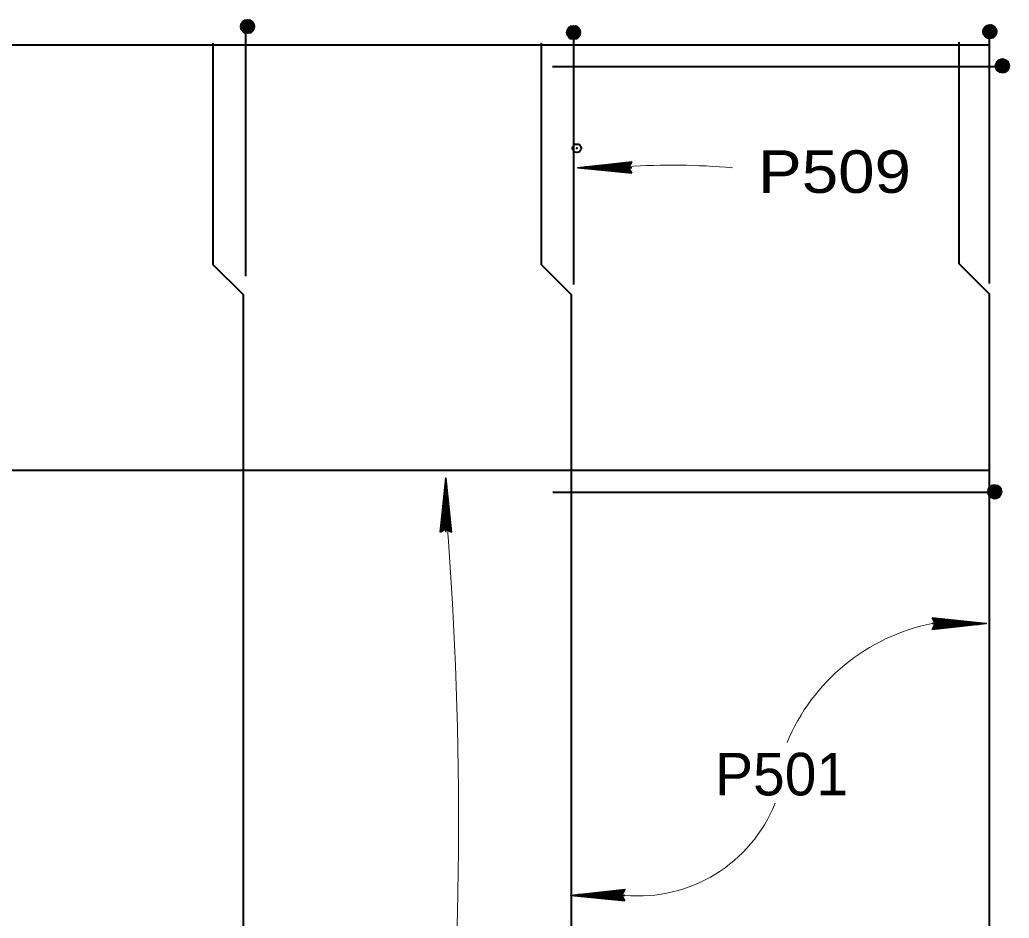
# Model space of a CAD drawing. Extents: x 6.34 to 9.53, y -1.46 to 0.53.
# Drawn here: x 7.1006 to 7.2943, y -0.5784 to -0.4024 of the extents above; entities that cross this region are included whole.
import ezdxf

# ---------------------------------------------------------------- set-up
doc = ezdxf.new("R2010")
doc.units = 0
doc.header["$LTSCALE"] = 0.0033
doc.header["$PDMODE"] = 32
doc.header["$PDSIZE"] = 0.00165
doc.layers.add('1', color=7, linetype='Continuous', lineweight=40)

msp = doc.modelspace()

# ---------------------------------------------------------------- linework, layer by layer
at = {"layer": '1'}
for p, q in [((7.14425, -0.404583), (7.144583, -0.402667)), ((7.144417, -0.404667), (7.14475, -0.402667)), ((7.1445, -0.402583), (7.146, -0.402667)), ((7.1445, -0.404667), (7.144833, -0.402667)), ((7.1445, -0.40275), (7.146, -0.402833)), ((7.1445, -0.402833), (7.146, -0.402917)), ((7.1445, -0.402917), (7.146, -0.403)), ((7.144583, -0.404667), (7.145, -0.402667)), ((7.144667, -0.404667), (7.145083, -0.402667)), ((7.144833, -0.404667), (7.145167, -0.40275)), ((7.144917, -0.40475), (7.14525, -0.40275)), ((7.145, -0.40475), (7.145417, -0.40275)), ((7.145083, -0.40475), (7.1455, -0.402833)), ((7.145167, -0.40475), (7.145583, -0.402833)), ((7.145333, -0.404833), (7.14575, -0.402833)), ((7.145583, -0.404833), (7.145917, -0.402833)), ((7.145667, -0.404833), (7.146, -0.402917)), ((7.14575, -0.404833), (7.146083, -0.402917)), ((7.145833, -0.404917), (7.146167, -0.402917)), ((7.144417, -0.403667), (7.145917, -0.40375)), ((7.144417, -0.40375), (7.145917, -0.403833)), ((7.144417, -0.403833), (7.145917, -0.403917)), ((7.144417, -0.403917), (7.145917, -0.404)), ((7.144417, -0.404), (7.145917, -0.404083)), ((7.144417, -0.404083), (7.145917, -0.404167)), ((7.144417, -0.404167), (7.145917, -0.40425)), ((7.144417, -0.404333), (7.145917, -0.404417)), ((7.144417, -0.404417), (7.145917, -0.4045)), ((7.144417, -0.4045), (7.145917, -0.404583)), ((7.144417, -0.404583), (7.145917, -0.404667)), ((7.144417, -0.404667), (7.145917, -0.40475)), ((7.1445, -0.403), (7.146, -0.403083)), ((7.1445, -0.403083), (7.146, -0.403167)), ((7.1445, -0.403167), (7.146, -0.40325)), ((7.1445, -0.40325), (7.146, -0.403333)), ((7.1445, -0.40325), (7.146, -0.403333)), ((7.1445, -0.403333), (7.146, -0.4035)), ((7.1445, -0.4035), (7.146, -0.403667)), ((7.144833, -0.403333), (7.144833, -0.452667)), ((7.208083, -0.40575), (7.208417, -0.403833)), ((7.20825, -0.405833), (7.208583, -0.403833)), ((7.20825, -0.404833), (7.20975, -0.404917)), ((7.208333, -0.40375), (7.209833, -0.403833)), ((7.208333, -0.405833), (7.208667, -0.403833)), ((7.208333, -0.403917), (7.209833, -0.404)), ((7.208333, -0.404), (7.209833, -0.404083)), ((7.208333, -0.404083), (7.209833, -0.404167)), ((7.208333, -0.404167), (7.209833, -0.40425)), ((7.208333, -0.40425), (7.209833, -0.404333)), ((7.208333, -0.404333), (7.209833, -0.404417)), ((7.208333, -0.404417), (7.209833, -0.4045)), ((7.208333, -0.404417), (7.209833, -0.4045)), ((7.208333, -0.4045), (7.209833, -0.404667)), ((7.208333, -0.404667), (7.209833, -0.404833)), ((7.208417, -0.405833), (7.208833, -0.403833)), ((7.2085, -0.405833), (7.208917, -0.403833)), ((7.208667, -0.405833), (7.209, -0.403917)), ((7.20875, -0.405917), (7.209083, -0.403917)), ((7.208833, -0.405917), (7.20925, -0.403917)), ((7.208917, -0.405917), (7.209333, -0.404)), ((7.209, -0.405917), (7.209417, -0.404)), ((7.209167, -0.406), (7.209583, -0.404)), ((7.209417, -0.406), (7.20975, -0.404)), ((7.2095, -0.406), (7.209833, -0.404083)), ((7.209583, -0.406), (7.209917, -0.404083)), ((7.209667, -0.406083), (7.21, -0.404083)), ((7.289583, -0.405583), (7.289917, -0.403667)), ((7.28975, -0.405667), (7.290083, -0.403667)), ((7.28975, -0.404667), (7.29125, -0.40475)), ((7.28975, -0.40475), (7.29125, -0.404833)), ((7.28975, -0.404833), (7.29125, -0.404917)), ((7.289833, -0.403583), (7.291333, -0.403667)), ((7.289833, -0.405667), (7.290167, -0.403667)), ((7.289833, -0.40375), (7.291333, -0.403833)), ((7.289833, -0.403833), (7.291333, -0.403917)), ((7.289833, -0.403917), (7.291333, -0.404)), ((7.289833, -0.404), (7.291333, -0.404083)), ((7.289833, -0.404083), (7.291333, -0.404167)), ((7.289833, -0.404167), (7.291333, -0.40425)), ((7.289833, -0.40425), (7.291333, -0.404333)), ((7.289833, -0.40425), (7.291333, -0.404333)), ((7.289833, -0.404333), (7.291333, -0.4045)), ((7.289833, -0.4045), (7.291333, -0.404667)), ((7.289917, -0.405667), (7.290333, -0.403667)), ((7.29, -0.405667), (7.290417, -0.403667)), ((7.290167, -0.405667), (7.2905, -0.40375)), ((7.29025, -0.40575), (7.290583, -0.40375)), ((7.290333, -0.40575), (7.29075, -0.40375)), ((7.290417, -0.40575), (7.290833, -0.403833)), ((7.290417, -0.40475), (7.290417, -0.454083)), ((7.2905, -0.40575), (7.290917, -0.403833)), ((7.290667, -0.405833), (7.291083, -0.403833)), ((7.290917, -0.405833), (7.29125, -0.403833)), ((7.291, -0.405833), (7.291333, -0.403917)), ((7.291083, -0.405833), (7.291417, -0.403917)), ((7.291167, -0.405917), (7.2915, -0.403917)), ((7.20825, -0.404917), (7.20975, -0.405)), ((7.20825, -0.405), (7.20975, -0.405083)), ((7.20825, -0.405083), (7.20975, -0.405167)), ((7.20825, -0.405167), (7.20975, -0.40525)), ((7.20825, -0.40525), (7.20975, -0.405333)), ((7.20825, -0.405333), (7.20975, -0.405417)), ((7.20825, -0.4055), (7.20975, -0.405583)), ((7.20825, -0.405583), (7.20975, -0.405667)), ((7.20825, -0.405667), (7.20975, -0.40575)), ((7.20825, -0.40575), (7.20975, -0.405833)), ((7.20825, -0.405833), (7.20975, -0.405917)), ((7.209, -0.404917), (7.209, -0.45425)), ((7.28975, -0.404917), (7.29125, -0.405)), ((7.28975, -0.405), (7.29125, -0.405083)), ((7.28975, -0.405083), (7.29125, -0.405167)), ((7.28975, -0.405167), (7.29125, -0.40525)), ((7.28975, -0.405333), (7.29125, -0.405417)), ((7.28975, -0.405417), (7.29125, -0.4055)), ((7.28975, -0.4055), (7.29125, -0.405583)), ((7.28975, -0.405583), (7.29125, -0.405667)), ((7.28975, -0.405667), (7.29125, -0.40575)), ((7.291833, -0.412167), (7.291917, -0.410667)), ((7.292, -0.412167), (7.292083, -0.410667)), ((7.292083, -0.412167), (7.292167, -0.410667)), ((7.294167, -0.410833), (7.292167, -0.4105)), ((7.294083, -0.410917), (7.292167, -0.410583)), ((7.292167, -0.412167), (7.29225, -0.410667)), ((7.294083, -0.411), (7.292167, -0.410667)), ((7.29225, -0.412167), (7.292333, -0.410667)), ((7.292333, -0.412167), (7.292417, -0.410667)), ((7.292417, -0.412167), (7.2925, -0.410667)), ((7.2925, -0.412167), (7.292583, -0.410667)), ((7.2925, -0.412167), (7.292583, -0.410667)), ((7.292583, -0.412167), (7.29275, -0.410667)), ((7.29275, -0.412167), (7.292917, -0.410667)), ((7.204917, -0.411583), (7.293, -0.411583)), ((7.207333, -0.411583), (7.293, -0.411583)), ((7.293917, -0.412), (7.291917, -0.411583)), ((7.293917, -0.412083), (7.291917, -0.411667)), ((7.293917, -0.412167), (7.291917, -0.411833)), ((7.293917, -0.41225), (7.291917, -0.411917)), ((7.293833, -0.412417), (7.291917, -0.412083)), ((7.294, -0.411667), (7.292, -0.41125)), ((7.294, -0.41175), (7.292, -0.411417)), ((7.293917, -0.411833), (7.292, -0.4115)), ((7.294083, -0.411083), (7.292083, -0.41075)), ((7.294083, -0.411333), (7.292083, -0.410917)), ((7.294, -0.4115), (7.292083, -0.411083)), ((7.294, -0.411583), (7.292083, -0.411167)), ((7.292917, -0.41225), (7.293, -0.41075)), ((7.293, -0.41225), (7.293083, -0.41075)), ((7.293083, -0.41225), (7.293167, -0.41075)), ((7.293167, -0.41225), (7.29325, -0.41075)), ((7.29325, -0.41225), (7.293333, -0.41075)), ((7.293333, -0.41225), (7.293417, -0.41075)), ((7.293417, -0.41225), (7.2935, -0.41075)), ((7.293583, -0.41225), (7.293667, -0.41075)), ((7.293667, -0.41225), (7.29375, -0.41075)), ((7.29375, -0.41225), (7.293833, -0.41075)), ((7.293833, -0.41225), (7.293917, -0.41075)), ((7.293917, -0.41225), (7.294, -0.41075)), ((6.962, -0.490667), (7.29025, -0.490667)), ((7.290667, -0.493917), (7.292583, -0.49425)), ((7.205, -0.494917), (7.290083, -0.494917)), ((7.290333, -0.4955), (7.292333, -0.495833)), ((7.290417, -0.495), (7.292417, -0.495417)), ((7.290417, -0.49525), (7.292417, -0.495583)), ((7.290417, -0.495333), (7.292333, -0.495667)), ((7.290417, -0.495417), (7.292333, -0.49575)), ((7.290583, -0.494083), (7.2905, -0.495583)), ((7.2905, -0.494583), (7.2925, -0.494917)), ((7.2905, -0.494667), (7.2925, -0.495083)), ((7.2905, -0.49475), (7.292417, -0.495167)), ((7.2905, -0.494833), (7.292417, -0.49525)), ((7.290667, -0.494083), (7.290583, -0.495583)), ((7.290583, -0.494083), (7.292583, -0.494417)), ((7.290583, -0.494167), (7.292583, -0.4945)), ((7.290583, -0.49425), (7.292583, -0.494667)), ((7.290583, -0.494333), (7.292583, -0.49475)), ((7.290583, -0.4945), (7.2925, -0.494833)), ((7.29075, -0.494083), (7.290667, -0.495583)), ((7.290833, -0.494083), (7.29075, -0.495583)), ((7.290917, -0.494083), (7.290833, -0.495583)), ((7.291083, -0.494083), (7.291, -0.495583)), ((7.291167, -0.494083), (7.291083, -0.495583)), ((7.29125, -0.494083), (7.291167, -0.495583)), ((7.291333, -0.494083), (7.29125, -0.495583)), ((7.291417, -0.494083), (7.291333, -0.495583)), ((7.2915, -0.494083), (7.291417, -0.495583)), ((7.291583, -0.494083), (7.2915, -0.495583)), ((7.29175, -0.494167), (7.291583, -0.495667)), ((7.291917, -0.494167), (7.29175, -0.495667)), ((7.292, -0.494167), (7.291917, -0.495667)), ((7.292, -0.494167), (7.291917, -0.495667)), ((7.292083, -0.494167), (7.292, -0.495667)), ((7.292167, -0.494167), (7.292083, -0.495667)), ((7.29225, -0.494167), (7.292167, -0.495667)), ((7.292333, -0.494167), (7.29225, -0.495667)), ((7.292417, -0.494167), (7.292333, -0.495667)), ((7.2925, -0.494167), (7.292417, -0.495667)), ((7.292667, -0.494167), (7.292583, -0.495667))]:
    msp.add_line(p, q, dxfattribs=at)
at = {"layer": '1', "lineweight": 35}
for p, q in [((7.220417, -0.431417), (7.209833, -0.431417)), ((7.220167, -0.43225), (7.212333, -0.43125)), ((7.220167, -0.43225), (7.212333, -0.431417)), ((7.220167, -0.432417), (7.212333, -0.4315)), ((7.220167, -0.432417), (7.212333, -0.4315)), ((7.220167, -0.432333), (7.212333, -0.4315)), ((7.220167, -0.430333), (7.212833, -0.431167)), ((7.220167, -0.4305), (7.212833, -0.43125)), ((7.220167, -0.430583), (7.212833, -0.431417)), ((7.22025, -0.43075), (7.212917, -0.4315)), ((7.184, -0.50275), (7.184, -0.492167)), ((7.183, -0.5025), (7.183917, -0.494667)), ((7.183, -0.5025), (7.183917, -0.494667)), ((7.183083, -0.5025), (7.183917, -0.494667)), ((7.183167, -0.5025), (7.184, -0.494667)), ((7.183167, -0.5025), (7.184167, -0.494667)), ((7.184667, -0.502583), (7.183917, -0.49525)), ((7.184833, -0.5025), (7.184, -0.495167)), ((7.184917, -0.5025), (7.184167, -0.495167)), ((7.185083, -0.5025), (7.18425, -0.495167)), ((7.27925, -0.520667), (7.289833, -0.520667)), ((7.279417, -0.521333), (7.28675, -0.520583)), ((7.2795, -0.519667), (7.287333, -0.520583)), ((7.2795, -0.519667), (7.287333, -0.520583)), ((7.2795, -0.51975), (7.287333, -0.520583)), ((7.2795, -0.519833), (7.287333, -0.520667)), ((7.2795, -0.519833), (7.287333, -0.520833)), ((7.2795, -0.5215), (7.286833, -0.520667)), ((7.2795, -0.521583), (7.286833, -0.520833)), ((7.2795, -0.52175), (7.286833, -0.520917)), ((7.218833, -0.572833), (7.2115, -0.573667)), ((7.218833, -0.573), (7.2115, -0.57375)), ((7.218833, -0.573083), (7.2115, -0.573917)), ((7.218917, -0.57325), (7.211583, -0.574)), ((7.219083, -0.573917), (7.2085, -0.573917)), ((7.218833, -0.57475), (7.211, -0.57375)), ((7.218833, -0.57475), (7.211, -0.573917)), ((7.218833, -0.574917), (7.211, -0.574)), ((7.218833, -0.574917), (7.211, -0.574)), ((7.218833, -0.574833), (7.211, -0.574))]:
    msp.add_line(p, q, dxfattribs=at)
at = {"layer": '1'}
for points in [[(7.14525, -0.405083), (7.144917, -0.4025), (7.144417, -0.404833), (7.1455, -0.4025), (7.145917, -0.404917), (7.14625, -0.402917), (7.144167, -0.402917), (7.1465, -0.403833), (7.143917, -0.403583), (7.14625, -0.404583), (7.143917, -0.40425), (7.1465, -0.403417), (7.14475, -0.405), (7.144583, -0.402583), (7.146417, -0.40425), (7.144, -0.403167), (7.144417, -0.404833), (7.145917, -0.404917), (7.1465, -0.403833), (7.14625, -0.402917), (7.1455, -0.4025), (7.144583, -0.402583), (7.144, -0.403167), (7.145083, -0.403833), (7.146, -0.402667), (7.14625, -0.404583), (7.145083, -0.403833), (7.144583, -0.404917), (7.143917, -0.403917), (7.145, -0.403833), (7.14625, -0.403), (7.145, -0.405), (7.144667, -0.403667), (7.144167, -0.402917)], [(7.209083, -0.40625), (7.20875, -0.403667), (7.20825, -0.406), (7.209333, -0.403667), (7.20975, -0.406083), (7.210083, -0.404083), (7.208, -0.404083), (7.210333, -0.405), (7.20775, -0.40475), (7.210083, -0.40575), (7.20775, -0.405417), (7.210333, -0.404583), (7.208583, -0.406167), (7.208417, -0.40375), (7.21025, -0.405417), (7.207833, -0.404333), (7.20825, -0.406), (7.20975, -0.406083), (7.210333, -0.405), (7.210083, -0.404083), (7.209333, -0.403667), (7.208417, -0.40375), (7.207833, -0.404333), (7.208917, -0.405), (7.209833, -0.403833), (7.210083, -0.40575), (7.208917, -0.405), (7.208417, -0.406083), (7.20775, -0.405083), (7.208833, -0.405), (7.210083, -0.404167), (7.208833, -0.406167), (7.2085, -0.404833), (7.208, -0.404083)], [(7.290583, -0.406083), (7.29025, -0.4035), (7.28975, -0.405833), (7.290833, -0.4035), (7.29125, -0.405917), (7.291583, -0.403917), (7.2895, -0.403917), (7.291833, -0.404833), (7.28925, -0.404583), (7.291583, -0.405583), (7.28925, -0.40525), (7.291833, -0.404417), (7.290083, -0.406), (7.289917, -0.403583), (7.29175, -0.40525), (7.289333, -0.404167), (7.28975, -0.405833), (7.29125, -0.405917), (7.291833, -0.404833), (7.291583, -0.403917), (7.290833, -0.4035), (7.289917, -0.403583), (7.289333, -0.404167), (7.290417, -0.404833), (7.291333, -0.403667), (7.291583, -0.405583), (7.290417, -0.404833), (7.289917, -0.405917), (7.28925, -0.404917), (7.290333, -0.404833), (7.291583, -0.404), (7.290333, -0.406), (7.29, -0.404667), (7.2895, -0.403917)], [(6.736667, -0.407333), (6.962167, -0.407333), (7.290333, -0.407333)], [(7.138417, -0.407), (7.138417, -0.450333), (7.144333, -0.45625), (7.144333, -0.664583), (7.138417, -0.6705), (7.138417, -0.71675)], [(7.202667, -0.407), (7.202667, -0.450333), (7.208583, -0.45625), (7.208583, -0.664583), (7.202667, -0.6705), (7.202667, -0.71675)], [(7.2845, -0.406833), (7.2845, -0.450167), (7.290417, -0.456083), (7.290417, -0.664417), (7.2845, -0.670333), (7.2845, -0.716583)], [(7.294333, -0.411417), (7.29175, -0.41175), (7.294083, -0.41225), (7.29175, -0.411167), (7.294167, -0.41075), (7.292167, -0.410417), (7.292167, -0.4125), (7.293083, -0.410167), (7.292833, -0.41275), (7.293833, -0.410417), (7.2935, -0.41275), (7.292667, -0.410167), (7.29425, -0.411917), (7.291833, -0.412083), (7.2935, -0.41025), (7.292417, -0.412667), (7.294083, -0.41225), (7.294167, -0.41075), (7.293083, -0.410167), (7.292167, -0.410417), (7.29175, -0.411167), (7.291833, -0.412083), (7.292417, -0.412667), (7.293083, -0.411583), (7.291917, -0.410667), (7.293833, -0.410417), (7.293083, -0.411583), (7.294167, -0.412083), (7.293167, -0.41275), (7.293083, -0.411667), (7.29225, -0.410417), (7.29425, -0.411667), (7.292917, -0.412), (7.292167, -0.4125)], [(7.290167, -0.494917), (7.29275, -0.494583), (7.290417, -0.494083), (7.29275, -0.495167), (7.290333, -0.495583), (7.292333, -0.495917), (7.292333, -0.493833), (7.291417, -0.496167), (7.291667, -0.493583), (7.290667, -0.495917), (7.291, -0.493583), (7.291833, -0.496167), (7.29025, -0.494417), (7.292667, -0.49425), (7.291, -0.496083), (7.292083, -0.493667), (7.290417, -0.494083), (7.290333, -0.495583), (7.291417, -0.496167), (7.292333, -0.495917), (7.29275, -0.495167), (7.292667, -0.49425), (7.292083, -0.493667), (7.291417, -0.49475), (7.292583, -0.495667), (7.290667, -0.495917), (7.291417, -0.49475), (7.290333, -0.49425), (7.291333, -0.493583), (7.291417, -0.494667), (7.29225, -0.495917), (7.29025, -0.494667), (7.291583, -0.494333), (7.292333, -0.493833)]]:
    msp.add_lwpolyline(points, dxfattribs=at)
at = {"layer": '1', "lineweight": 35}
for points in [[(7.220417, -0.4325), (7.209833, -0.431417), (7.220417, -0.43025), (7.219833, -0.431417)], [(7.219667, -0.4315), (7.215, -0.431583), (7.215, -0.4315), (7.215917, -0.4315), (7.219667, -0.431583), (7.216667, -0.431667), (7.219833, -0.43175), (7.217583, -0.431833), (7.219833, -0.431917), (7.216333, -0.431667), (7.211667, -0.4315), (7.212583, -0.43125), (7.211333, -0.43125), (7.219667, -0.43125), (7.21725, -0.431083), (7.219833, -0.431083), (7.2145, -0.4315), (7.219833, -0.430833)], [(7.182917, -0.50275), (7.184, -0.492167), (7.185167, -0.50275), (7.184, -0.502167)], [(7.183917, -0.502), (7.183833, -0.497333), (7.183917, -0.497333), (7.183917, -0.49825), (7.183833, -0.502), (7.18375, -0.499), (7.183667, -0.502167), (7.183583, -0.499917), (7.1835, -0.502167), (7.18375, -0.498667), (7.183917, -0.494), (7.184167, -0.494917), (7.184167, -0.493667), (7.184167, -0.502), (7.184333, -0.499583), (7.184333, -0.502167), (7.183917, -0.496833), (7.184583, -0.502167)], [(7.27925, -0.519583), (7.289833, -0.520667), (7.27925, -0.521833), (7.279833, -0.520667)], [(7.28, -0.520583), (7.284667, -0.5205), (7.284667, -0.520583), (7.28375, -0.520583), (7.28, -0.5205), (7.283, -0.520417), (7.279833, -0.520333), (7.282083, -0.52025), (7.279833, -0.520167), (7.283333, -0.520417), (7.288, -0.520583), (7.287083, -0.520833), (7.288333, -0.520833), (7.28, -0.520833), (7.282417, -0.521), (7.279833, -0.521), (7.285167, -0.520583), (7.279833, -0.52125)], [(7.219083, -0.575), (7.2085, -0.573917), (7.219083, -0.57275), (7.2185, -0.573917)], [(7.218333, -0.574), (7.213667, -0.574083), (7.213667, -0.574), (7.214583, -0.574), (7.218333, -0.574083), (7.215333, -0.574167), (7.2185, -0.57425), (7.21625, -0.574333), (7.2185, -0.574417), (7.215, -0.574167), (7.210333, -0.574), (7.21125, -0.57375), (7.21, -0.57375), (7.218333, -0.57375), (7.215917, -0.573583), (7.2185, -0.573583), (7.213167, -0.574), (7.2185, -0.573333)]]:
    msp.add_lwpolyline(points, close=True, dxfattribs=at)
for points in [[(7.219667, -0.4315), (7.220083, -0.43225), (7.219833, -0.432), (7.219667, -0.431667), (7.219417, -0.43175), (7.219583, -0.432083), (7.21975, -0.431333), (7.219917, -0.430833), (7.220167, -0.430417)], [(7.183917, -0.502), (7.183167, -0.502417), (7.183417, -0.502167), (7.18375, -0.502), (7.183667, -0.50175), (7.183333, -0.501917), (7.184083, -0.502083), (7.184583, -0.50225), (7.185, -0.5025)], [(7.28, -0.520583), (7.279583, -0.519833), (7.279833, -0.520083), (7.28, -0.520417), (7.28025, -0.520333), (7.280083, -0.52), (7.279917, -0.52075), (7.27975, -0.52125), (7.2795, -0.521667)], [(7.218333, -0.574), (7.21875, -0.57475), (7.2185, -0.5745), (7.218333, -0.574167), (7.218083, -0.57425), (7.21825, -0.574583), (7.218417, -0.573833), (7.218583, -0.573333), (7.218833, -0.572917)]]:
    msp.add_lwpolyline(points, dxfattribs=at)
at = {"layer": '1'}
for centre in [(7.1452, -0.40375), (7.209033, -0.404917), (7.290533, -0.40475), (7.293, -0.411467), (7.2915, -0.494867)]:
    msp.add_circle(centre, 0.00132, dxfattribs=at)
at = {"layer": '1', "lineweight": 13}
for centre, radius, start, end in [((7.228156, -0.569921), 0.139025, 85.04405, 93.56983), ((6.434053, -0.558971), 0.752466, 354.58985, 4.45032), ((7.286942, -0.559005), 0.039102, 101.34497, 157.43485), ((7.221703, -0.54521), 0.028826, 264.78548, 338.37517)]:
    msp.add_arc(centre, radius, start, end, dxfattribs=at)
at = {"layer": '1'}
msp.add_point((7.209667, -0.427583), dxfattribs=at)

# ---------------------------------------------------------------- texts
at = {"layer": '1', "width": 1.15}
msp.add_text('P509', height=0.008334, dxfattribs=at).set_placement((7.245167, -0.436333))
at = {"layer": '1'}
msp.add_text('P501', height=0.008334, dxfattribs=at).set_placement((7.23675, -0.554333))

doc.saveas('drawing.dxf')
